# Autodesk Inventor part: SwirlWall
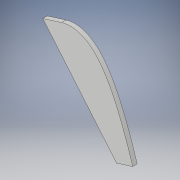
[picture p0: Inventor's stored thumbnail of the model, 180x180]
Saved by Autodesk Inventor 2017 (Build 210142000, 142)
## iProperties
Created: 2017-05
Part Number: SwirlWall
Material: Generic
Document SubType Name: Modeling
Designer: 1460374
Density: 1 g/cm^3
Appearance: Default
Author: 1460374
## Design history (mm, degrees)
sketch "Sketch1"
  geometry: L1 (-26.808, 32.526)-(-40.164, 28.33) reference; L2 (24.03, -31.119)-(12.478, -34.749); L3 (12.478, -34.749)-(-40.164, 28.33); 1 further point
  constraints: 4 end point
  dimensions: "d2" = 82.15891 distance of L2.end L1.end
extrude "Extrusion1" new body sketch "Sketch1" distance "d0" = 3.175; taper "d1" = 0 deg
body "Solid1"
node "Reference1"
node "Reference2"
